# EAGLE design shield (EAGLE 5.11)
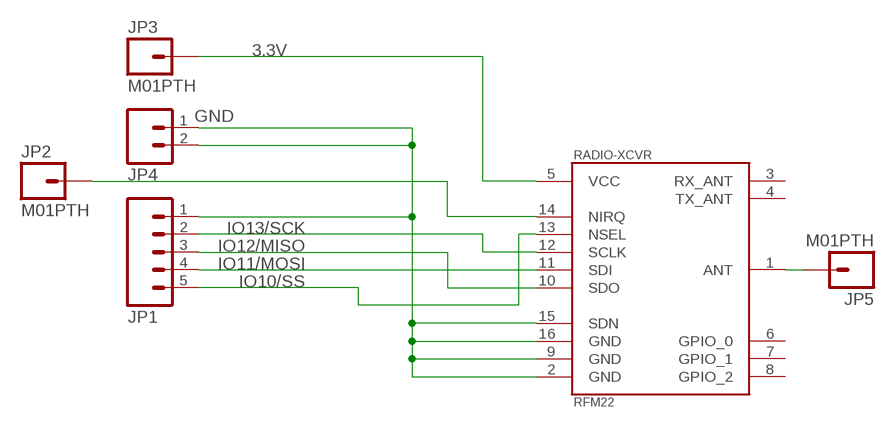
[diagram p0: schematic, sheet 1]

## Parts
JP1  M05PTH  [1X05]
JP2  M01PTH  [1X01]
JP3  M01PTH  [1X01]
JP4  M02PTH  [1X02]
JP5  M01PTH  [1X01]
RADIO-XCVR  RFM22  [RFM22-XXX-S2]

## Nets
3.3V: JP3.1 RADIO-XCVR.5(VCC)
ANT: JP5.1 RADIO-XCVR.1(ANT)
GND: JP1.1 JP4.1 JP4.2 RADIO-XCVR.2(GND) RADIO-XCVR.9(GND) RADIO-XCVR.15(SDN) RADIO-XCVR.16(GND)
IO2: JP2.1 RADIO-XCVR.14(NIRQ)
IO10/SS: JP1.5 RADIO-XCVR.13(NSEL)
IO11/MOSI: JP1.4 RADIO-XCVR.11(SDI)
IO12/MISO: JP1.3 RADIO-XCVR.10(SDO)
IO13/SCK: JP1.2 RADIO-XCVR.12(SCLK)
Unconnected: RADIO-XCVR.3(RX_ANT) RADIO-XCVR.4(TX_ANT) RADIO-XCVR.6(GPIO_0) RADIO-XCVR.7(GPIO_1) RADIO-XCVR.8(GPIO_2)

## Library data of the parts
JP1 = SparkFun:M05: Header 5 Standard 5-pin 0.1" header. Use with straight break away headers (SKU : PRT-00116), right angle break away headers (PRT-00553), swiss pins (PRT-00743), machine pins (PRT-00117), and female headers (PRT-00115). Molex polarized connector foot print use with SKU : PRT-08230 with associated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
JP2 JP3 JP5 = SparkFun:M01: Header 1
JP4 = SparkFun:M02: Header 2
RADIO-XCVR = SparkFun2011-02-20:RFM22: *Hope RF's RFM22* Packages: RFM22-S2 (SMD)

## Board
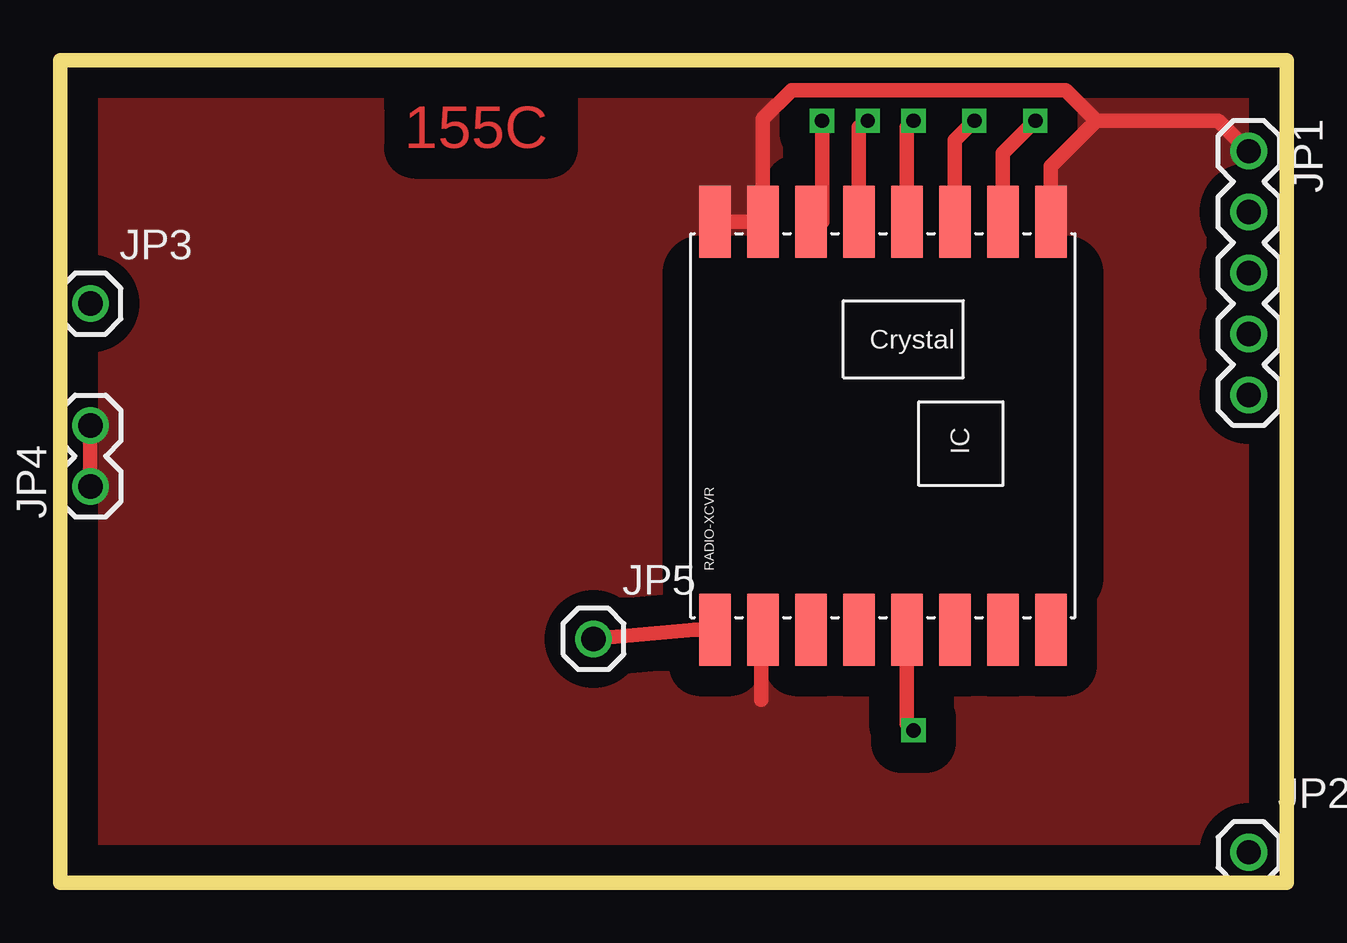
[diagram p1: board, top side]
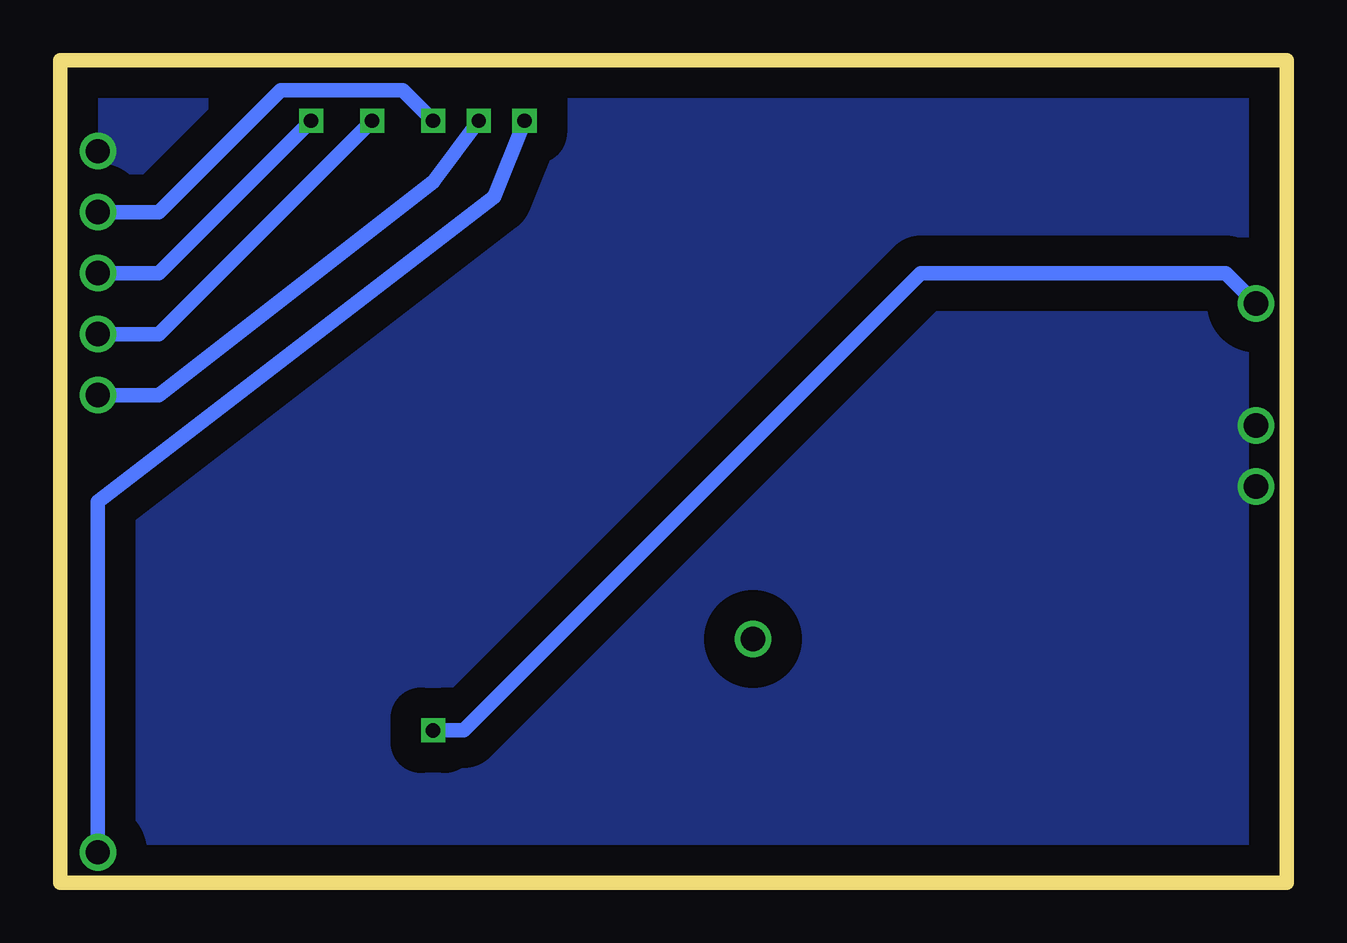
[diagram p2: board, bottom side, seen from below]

Size 51.1 x 34.28 mm. Coordinates in mm from the lower left corner, seen from the top.
Outline: 0,0 51.1,0 51.1,34.28 0,34.28 0,0
Copper layers (1*16): Top 0.035mm / dielectric 1.5mm / Bottom 0.035mm
Design rules "default": minimum track width 10mil, minimum drill 24mil, track to track 8mil, track to pad 8mil, pad to pad 8mil, via to via 8mil, smd to smd 8mil, copper to edge 40mil, drill to drill 8mil, minimum pad ring 10mil, minimum via ring 8mil, stop-mask expansion 4mil, vias tented up to drill 0mil, thermal gap 10mil
tRestrict: area 26.7,12.7 to 41.9,25.4

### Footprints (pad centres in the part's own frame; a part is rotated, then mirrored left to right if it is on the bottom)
1X05 = drill 1.016 round: 1 0,0; 2 2.54,0; 3 5.08,0; 4 7.62,0; 5 10.16,0
1X01 = drill 1.016 round: 1 0,0
1X02 = drill 1.016 round: 1 0,0; 2 2.54,0
RFM22-XXX-S2 = smd 3 x 1.3: 1 -8.5,7; 2 -8.5,5; 3 -8.5,3; 4 -8.5,1; 5 -8.5,-1; 6 -8.5,-3; 7 -8.5,-5; 8 -8.5,-7; 9 8.5,-7; 10 8.5,-5; 11 8.5,-3; 12 8.5,-1; 13 8.5,1; 14 8.5,3; 15 8.5,5; 16 8.5,7

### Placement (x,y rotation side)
JP1  49.53,30.48 270 top
JP2  49.53,1.27 0 top
JP3  1.27,24.13 0 top
JP4  1.27,16.51 90 top
JP5  22.23,10.16 0 top
RADIO-XCVR  34.29,19.05 90 top

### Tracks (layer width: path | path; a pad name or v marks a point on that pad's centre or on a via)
3.3V  (via drill 0.6)
  Top 0.61: RADIO-XCVR.5 35.29,6.62 v35.56,6.35
  Bottom 0.61: v35.56,6.35 34.29,6.35 15.24,25.4 2.54,25.4 JP3.1
ANT
  Top 0.61: RADIO-XCVR.1 26.43,10.55 JP5.1
GND
  Top 0.61: RADIO-XCVR.16 RADIO-XCVR.15 29.29,31.83 30.48,33.02 41.91,33.02 43.18,31.75 | JP4.1 JP4.2 | RADIO-XCVR.9 41.29,29.86 43.18,31.75 | 43.18,31.75 48.26,31.75 JP1.1 | RADIO-XCVR.2 29.21,10.55 29.21,7.62
  pour Top (isolate 1.27, no thermals): 0,34.29 50.8,34.29 50.8,0 0,0
  pour Bottom (isolate 1.27, no thermals): 0,34.29 50.8,34.29 50.8,0 0,0
IO2  (via drill 0.6)
  Top 0.61: RADIO-XCVR.14 31.75,27.55 v31.75,31.75
  Bottom 0.61: v31.75,31.75 33.02,28.57 49.53,15.88 JP2.1
IO10/SS  (via drill 0.6)
  Top 0.61: RADIO-XCVR.13 33.29,31.48 v33.66,31.75
  Bottom 0.61: v33.66,31.75 35.56,29.21 46.99,20.32 JP1.5
IO11/MOSI  (via drill 0.6)
  Top 0.61: RADIO-XCVR.11 37.29,30.94 v38.1,31.75
  Bottom 0.61: v38.1,31.75 46.99,22.86 JP1.4
IO12/MISO  (via drill 0.6)
  Top 0.61: RADIO-XCVR.10 39.29,30.4 v40.64,31.75
  Bottom 0.61: v40.64,31.75 46.99,25.4 JP1.3
IO13/SCK  (via drill 0.6)
  Top 0.61: RADIO-XCVR.12 35.29,31.48 v35.56,31.75
  Bottom 0.61: v35.56,31.75 36.83,33.02 41.91,33.02 46.99,27.94 JP1.2

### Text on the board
Top: 155C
